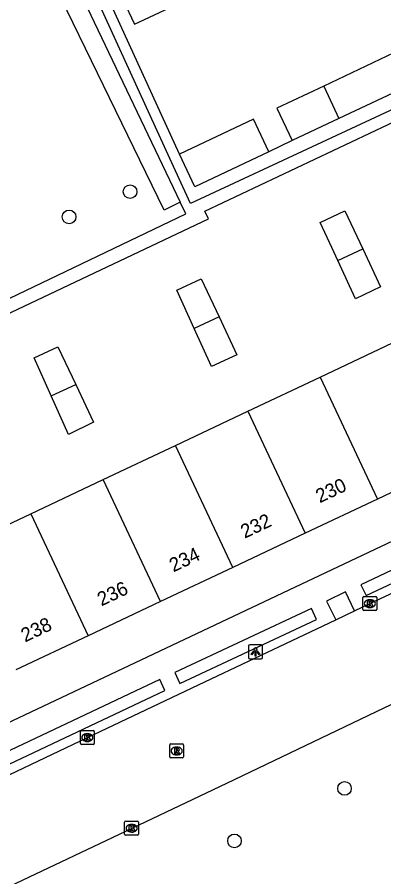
# Model space of a CAD drawing. Extents: x 159040 to 160094, y 381214 to 382518.
# Drawn here: x 159217.7 to 159244, y 381319.6 to 381381.3 of the extents above; entities that cross this region are included whole.
import ezdxf

# ---------------------------------------------------------------- set-up
doc = ezdxf.new("R2010")
doc.units = 0
for name, color, linetype in [('IMGEO_Boom', 7, 'Continuous'), ('IMGEO_Groenvoorziening', 7, 'Continuous'), ('IMGEO_Kolk', 7, 'Continuous'), ('IMGEO_Lichtpunt', 7, 'Continuous'), ('IMGEO_Pand', 7, 'Continuous'), ('IMGEO_Pand_nummerreeks', 7, 'Continuous'), ('IMGEO_Rijbaan_lokaal_gesloten', 7, 'Continuous'), ('IMGEO_Rioolput', 7, 'Continuous'), ('IMGEO_Voetpad_open', 7, 'Continuous')]:
    doc.layers.add(name, color=color, linetype=linetype)

msp = doc.modelspace()

# ---------------------------------------------------------------- linework, layer by layer
at = {"layer": 'IMGEO_Boom'}
for centre in [(159225.781, 381368.741), (159221.399, 381366.935), (159241.175, 381325.955), (159233.273, 381322.194)]:
    msp.add_circle(centre, 0.489, dxfattribs=at)
at = {"layer": 'IMGEO_Groenvoorziening'}
for points in [[(159229.381, 381367.981), (159228.231, 381367.404), (159219.083, 381386.197), (159219.616, 381388.419)], [(159229.323, 381371.43), (159224.414, 381382.139)], [(159237.424, 381372.4), (159235.733, 381371.602)]]:
    msp.add_lwpolyline(points, dxfattribs=at)
at = {"layer": 'IMGEO_Kolk'}
for p, q in [((159242.496, 381338.78), (159242.496, 381339.632)), ((159242.571, 381339.706), (159243.423, 381339.706)), ((159242.984, 381339.486), (159243.009, 381339.486)), ((159243.497, 381339.632), (159243.497, 381338.78)), ((159243.423, 381338.706), (159242.571, 381338.706)), ((159243.007, 381338.926), (159242.982, 381338.926)), ((159222.208, 381329.172), (159222.208, 381330.024)), ((159222.283, 381330.098), (159223.135, 381330.098)), ((159222.696, 381329.878), (159222.721, 381329.878)), ((159223.209, 381330.024), (159223.209, 381329.172)), ((159222.719, 381329.318), (159222.694, 381329.318)), ((159223.135, 381329.098), (159222.283, 381329.098)), ((159225.385, 381322.673), (159225.385, 381323.525)), ((159225.46, 381323.599), (159226.312, 381323.599)), ((159225.873, 381323.379), (159225.898, 381323.379)), ((159226.386, 381323.525), (159226.386, 381322.673)), ((159226.312, 381322.599), (159225.46, 381322.599)), ((159225.896, 381322.819), (159225.871, 381322.819))]:
    msp.add_line(p, q, dxfattribs=at)
for points in [[(159242.496, 381338.78), (159242.496, 381339.632)], [(159242.571, 381339.706), (159243.423, 381339.706)], [(159242.817, 381339.406), (159242.94, 381339.406), (159242.94, 381339.255), (159243.07, 381339.406), (159243.234, 381339.406), (159243.088, 381339.255), (159243.241, 381339.006), (159243.089, 381339.006), (159243.004, 381339.17), (159242.94, 381339.103), (159242.94, 381339.006), (159242.817, 381339.006), (159242.817, 381339.406)], [(159243.497, 381339.632), (159243.497, 381338.78)], [(159243.423, 381338.706), (159242.571, 381338.706)], [(159222.208, 381329.172), (159222.208, 381330.024)], [(159222.283, 381330.098), (159223.135, 381330.098)], [(159223.209, 381330.024), (159223.209, 381329.172)], [(159222.529, 381329.798), (159222.652, 381329.798), (159222.652, 381329.647), (159222.782, 381329.798), (159222.946, 381329.798), (159222.8, 381329.647), (159222.953, 381329.398), (159222.801, 381329.398), (159222.716, 381329.562), (159222.652, 381329.495), (159222.652, 381329.398), (159222.529, 381329.398), (159222.529, 381329.798)], [(159223.135, 381329.098), (159222.283, 381329.098)], [(159225.385, 381322.673), (159225.385, 381323.525)], [(159225.46, 381323.599), (159226.312, 381323.599)], [(159225.706, 381323.299), (159225.829, 381323.299), (159225.829, 381323.148), (159225.959, 381323.299), (159226.123, 381323.299), (159225.977, 381323.148), (159226.13, 381322.899), (159225.978, 381322.899), (159225.893, 381323.063), (159225.829, 381322.996), (159225.829, 381322.899), (159225.706, 381322.899), (159225.706, 381323.299)], [(159226.386, 381323.525), (159226.386, 381322.673)], [(159226.312, 381322.599), (159225.46, 381322.599)]]:
    msp.add_lwpolyline(points, dxfattribs=at)
for centre, start, end in [((159242.573, 381339.63), 91.55205, 178.44795), ((159242.573, 381339.63), 91.55205, 178.44795), ((159243.421, 381339.63), 1.55205, 88.44795), ((159243.421, 381339.63), 1.55205, 88.44795), ((159242.573, 381338.782), 181.55205, 268.44795), ((159242.573, 381338.782), 181.55205, 268.44795), ((159243.421, 381338.782), 271.55205, 358.44795), ((159243.421, 381338.782), 271.55205, 358.44795), ((159222.285, 381330.022), 91.55205, 178.44795), ((159222.285, 381330.022), 91.55205, 178.44795), ((159223.133, 381330.022), 1.55205, 88.44795), ((159223.133, 381330.022), 1.55205, 88.44795), ((159222.285, 381329.174), 181.55205, 268.44795), ((159222.285, 381329.174), 181.55205, 268.44795), ((159223.133, 381329.174), 271.55205, 358.44795), ((159223.133, 381329.174), 271.55205, 358.44795), ((159225.462, 381323.523), 91.55205, 178.44795), ((159225.462, 381323.523), 91.55205, 178.44795), ((159226.31, 381323.523), 1.55205, 88.44795), ((159226.31, 381323.523), 1.55205, 88.44795), ((159225.462, 381322.675), 181.55205, 268.44795), ((159225.462, 381322.675), 181.55205, 268.44795), ((159226.31, 381322.675), 271.55205, 358.44795), ((159226.31, 381322.675), 271.55205, 358.44795)]:
    msp.add_arc(centre, 0.0765, start, end, dxfattribs=at)
for centre, major_axis, ratio, start_param, end_param in [((159242.983, 381339.206), (-0.387, 0.002), 0.722429, 4.712389, 7.853982), ((159243.008, 381339.206), (-0.39, 0.002), 0.717154, 1.570796, 4.712389), ((159222.695, 381329.598), (-0.387, 0.002), 0.722429, 4.712389, 7.853982), ((159222.72, 381329.598), (-0.39, 0.002), 0.717154, 1.570796, 4.712389), ((159225.872, 381323.099), (-0.387, 0.002), 0.722429, 4.712389, 7.853982), ((159225.897, 381323.099), (-0.39, 0.002), 0.717154, 1.570796, 4.712389)]:
    msp.add_ellipse(centre, major_axis=major_axis, ratio=ratio, start_param=start_param, end_param=end_param, dxfattribs=at)
at = {"layer": 'IMGEO_Lichtpunt'}
for p, q in [((159234.284, 381336.151), (159234.284, 381335.344)), ((159234.284, 381336.151), (159234.284, 381335.344)), ((159235.186, 381336.246), (159234.378, 381336.246)), ((159235.186, 381336.246), (159234.378, 381336.246)), ((159235.28, 381335.344), (159235.28, 381336.151)), ((159235.28, 381335.344), (159235.28, 381336.151)), ((159234.378, 381335.25), (159235.186, 381335.25)), ((159234.378, 381335.25), (159235.186, 381335.25))]:
    msp.add_line(p, q, dxfattribs=at)
for points in [[(159234.658, 381335.815), (159234.697, 381335.787), (159234.509, 381335.525), (159234.471, 381335.552), (159234.658, 381335.815)], [(159234.76, 381335.767), (159234.807, 381335.767), (159234.807, 381335.445), (159234.76, 381335.445), (159234.76, 381335.767)], [(159234.87, 381335.787), (159234.908, 381335.814), (159235.095, 381335.552), (159235.056, 381335.524), (159234.87, 381335.787)]]:
    msp.add_lwpolyline(points, dxfattribs=at)
msp.add_circle((159234.783, 381335.949), 0.0994, dxfattribs=at)
for centre, start, end in [((159234.378, 381336.151), 90, 180), ((159234.378, 381336.151), 90, 180), ((159235.186, 381336.151), 0, 90), ((159235.186, 381336.151), 0, 90), ((159234.378, 381335.344), 180, 270), ((159234.378, 381335.344), 180, 270), ((159235.186, 381335.344), 270, 0), ((159235.186, 381335.344), 270, 360)]:
    msp.add_arc(centre, 0.0946, start, end, dxfattribs=at)
at = {"layer": 'IMGEO_Pand'}
for points in [[(159224.414, 381382.139), (159225.257, 381382.536), (159226.095, 381380.758), (159230.09, 381382.641), (159229.26, 381384.401), (159229.621, 381384.571)], [(159244.727, 381378.696), (159239.678, 381376.315)], [(159239.678, 381376.315), (159236.325, 381374.733), (159237.424, 381372.4)], [(159239.678, 381376.315), (159240.778, 381373.982)], [(159245.826, 381376.363), (159240.778, 381373.982)], [(159235.733, 381371.602), (159234.634, 381373.935), (159229.323, 381371.43)], [(159240.778, 381373.982), (159237.424, 381372.4)], [(159235.733, 381371.602), (159230.423, 381369.097), (159229.323, 381371.43)], [(159240.698, 381363.795), (159240.255, 381364.741), (159239.422, 381366.526), (159241.201, 381367.364), (159242.479, 381364.637)], [(159242.479, 381364.637), (159243.756, 381361.909), (159241.974, 381361.068), (159240.698, 381363.795)], [(159240.698, 381363.795), (159242.479, 381364.637)], [(159230.385, 381358.927), (159229.127, 381361.678), (159230.886, 381362.492), (159232.165, 381359.769)], [(159232.165, 381359.769), (159233.444, 381357.046), (159231.634, 381356.195), (159230.385, 381358.927)], [(159232.165, 381359.769), (159230.385, 381358.927)], [(159220.114, 381354.1), (159218.896, 381356.826), (159220.593, 381357.621), (159221.871, 381354.915)], [(159239.428, 381355.446), (159244.622, 381357.894)], [(159234.234, 381352.997), (159239.428, 381355.446)], [(159239.428, 381355.446), (159243.553, 381346.695)], [(159221.871, 381354.915), (159223.148, 381352.208), (159221.347, 381351.339), (159220.114, 381354.1)], [(159220.114, 381354.1), (159221.871, 381354.915)], [(159229.04, 381350.548), (159234.234, 381352.997)], [(159234.234, 381352.997), (159238.359, 381344.246)], [(159223.846, 381348.099), (159229.04, 381350.548)], [(159233.166, 381341.797), (159229.04, 381350.548)], [(159248.747, 381349.144), (159243.553, 381346.695)], [(159218.652, 381345.651), (159223.846, 381348.099)], [(159227.972, 381339.348), (159223.846, 381348.099)], [(159243.553, 381346.695), (159238.359, 381344.246)], [(159213.458, 381343.202), (159218.652, 381345.651)], [(159218.652, 381345.651), (159222.778, 381336.899)], [(159238.359, 381344.246), (159233.166, 381341.797)], [(159233.166, 381341.797), (159227.972, 381339.348)], [(159227.972, 381339.348), (159222.778, 381336.899)], [(159222.778, 381336.899), (159217.584, 381334.45)]]:
    msp.add_lwpolyline(points, dxfattribs=at)
at = {"layer": 'IMGEO_Rijbaan_lokaal_gesloten'}
for points in [[(159241.883, 381338.677), (159242.999, 381339.206), (159250.438, 381342.679), (159259.584, 381347.068), (159263.507, 381348.823), (159265.252, 381349.625), (159268.589, 381351.295)], [(159205.625, 381313.592), (159207.455, 381314.381), (159208.328, 381314.79), (159225.919, 381323.116), (159232.721, 381326.338), (159244.02, 381331.744), (159259.828, 381339.216), (159276.504, 381347.102), (159281.002, 381349.59)], [(159240.543, 381338.041), (159241.883, 381338.677)], [(159203.531, 381320.66), (159208.66, 381323.044), (159214.057, 381325.488), (159222.72, 381329.602), (159231.152, 381333.589), (159240.543, 381338.041)]]:
    msp.add_lwpolyline(points, dxfattribs=at)
at = {"layer": 'IMGEO_Rioolput'}
for p, q in [((159228.62, 381328.213), (159228.62, 381329.065)), ((159228.695, 381329.139), (159229.547, 381329.139)), ((159229.108, 381328.919), (159229.133, 381328.919)), ((159229.621, 381329.065), (159229.621, 381328.213)), ((159229.547, 381328.139), (159228.695, 381328.139)), ((159229.131, 381328.359), (159229.106, 381328.359))]:
    msp.add_line(p, q, dxfattribs=at)
for points in [[(159228.62, 381328.213), (159228.62, 381329.065)], [(159228.695, 381329.139), (159229.547, 381329.139)], [(159229.209, 381328.837), (159228.957, 381328.839), (159228.957, 381328.439)], [(159229.135, 381328.758), (159229.081, 381328.758), (159229.081, 381328.677)], [(159229.081, 381328.677), (159229.133, 381328.677)], [(159229.621, 381329.065), (159229.621, 381328.213)], [(159229.547, 381328.139), (159228.695, 381328.139)], [(159228.957, 381328.439), (159229.081, 381328.439), (159229.081, 381328.601), (159229.092, 381328.601)], [(159229.139, 381328.572), (159229.21, 381328.439), (159229.35, 381328.439), (159229.285, 381328.565)]]:
    msp.add_lwpolyline(points, dxfattribs=at)
for centre, radius, start, end in [((159228.697, 381329.063), 0.0765, 91.55205, 178.44795), ((159228.697, 381329.063), 0.0765, 91.55205, 178.44795), ((159229.117, 381328.866), 0.19, 274.7715, 282.96867), ((159229.141, 381328.662), 0.0964, 77.00612, 93.18647), ((159229.155, 381328.719), 0.0378, 276.66336, 79.67722), ((159229.208, 381328.727), 0.109, 350.36119, 89.41601), ((159229.206, 381328.727), 0.112, 277.58423, 350.98172), ((159229.545, 381329.063), 0.0765, 1.55205, 88.44795), ((159229.545, 381329.063), 0.0765, 1.55205, 88.44795), ((159228.697, 381328.215), 0.0765, 181.55205, 268.44795), ((159228.697, 381328.215), 0.0765, 181.55205, 268.44795), ((159229.091, 381328.548), 0.0533, 26.02933, 88.69889), ((159229.19, 381328.512), 0.108, 29.51342, 73.79051), ((159229.545, 381328.215), 0.0765, 271.55205, 358.44795), ((159229.545, 381328.215), 0.0765, 271.55205, 358.44795)]:
    msp.add_arc(centre, radius, start, end, dxfattribs=at)
for centre, major_axis, ratio, start_param, end_param in [((159229.107, 381328.639), (-0.387, 0.002), 0.722429, 4.712389, 7.853982), ((159229.132, 381328.639), (-0.39, 0.002), 0.717154, 1.570796, 4.712389)]:
    msp.add_ellipse(centre, major_axis=major_axis, ratio=ratio, start_param=start_param, end_param=end_param, dxfattribs=at)
at = {"layer": 'IMGEO_Voetpad_open'}
for points in [[(159267.21, 381385.165), (159261.509, 381382.51), (159230.12, 381367.891), (159228.641, 381371.117), (159220.151, 381389.64), (159219.711, 381390.599)], [(159219.616, 381388.419), (159218.973, 381389.765), (159211.368, 381358.351), (159229.779, 381367.148), (159229.381, 381367.981)], [(159219.616, 381388.419), (159229.381, 381367.981)], [(159187.998, 381346.282), (159210.414, 381356.868), (159231.408, 381366.79), (159231.151, 381367.335), (159246.942, 381374.798), (159261.829, 381381.834), (159267.618, 381384.57)], [(159279.522, 381361.378), (159273.546, 381357.821), (159271.62, 381356.674), (159265.823, 381353.699), (159204.502, 381324.76)], [(159242.338, 381340.559), (159242.727, 381339.778), (159255.527, 381345.783), (159255.163, 381346.588), (159242.338, 381340.559)], [(159241.883, 381338.677), (159241.237, 381340.045), (159239.888, 381339.379), (159240.543, 381338.041)], [(159229, 381334.272), (159229.357, 381333.472), (159239.16, 381338.056), (159238.806, 381338.862), (159229, 381334.272)], [(159216.733, 381328.47), (159217.104, 381327.683), (159228.28, 381332.966), (159227.907, 381333.773), (159216.733, 381328.47)]]:
    msp.add_lwpolyline(points, dxfattribs=at)

# ---------------------------------------------------------------- texts
at = {"layer": 'IMGEO_Pand_nummerreeks'}
for s, p in [('230', (159239.399, 381346.395)), ('232', (159234.006, 381343.852)), ('234', (159228.885, 381341.437)), ('236', (159223.717, 381339)), ('238', (159218.237, 381336.416))]:
    msp.add_text(s, height=1, rotation=25.24579, dxfattribs=at).set_placement(p)

doc.saveas('drawing.dxf')
